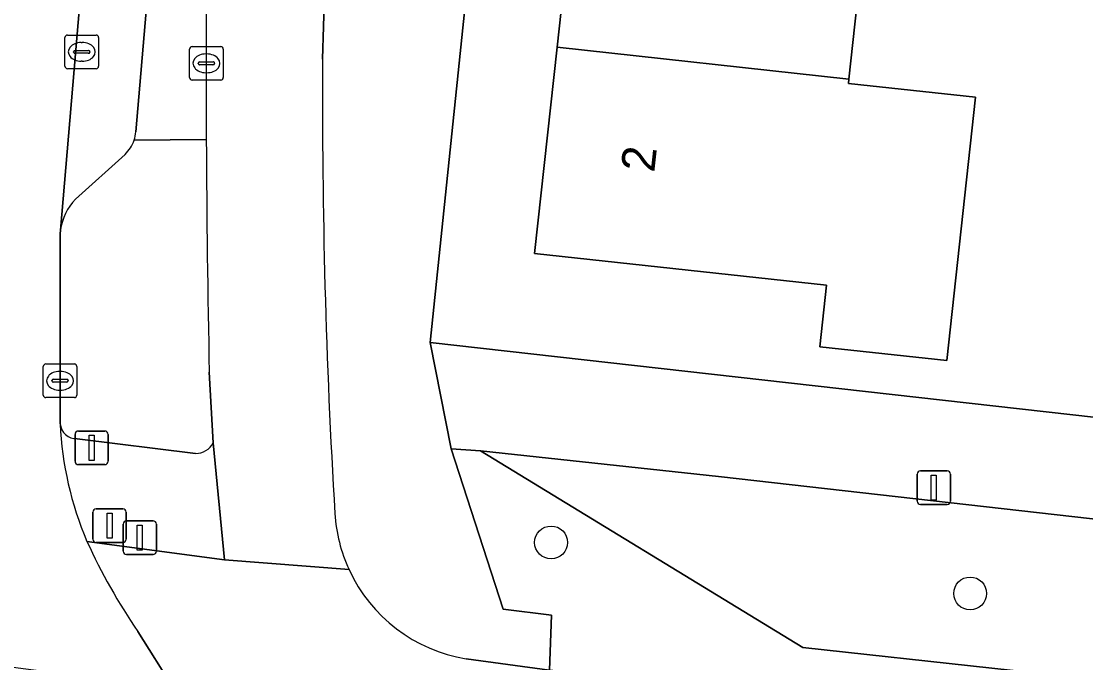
# Model space of a CAD drawing. Extents: x 161928 to 163071, y 386474 to 387428.
# Drawn here: x 162189.6 to 162221.3, y 386515.81 to 386534.9 of the extents above; entities that cross this region are included whole.
import ezdxf

# ---------------------------------------------------------------- set-up
doc = ezdxf.new("R2010")
doc.units = 0
for name, color, linetype in [('IMGEO_Boom', 7, 'Continuous'), ('IMGEO_Drukknoppaal', 7, 'Continuous'), ('IMGEO_Erf', 7, 'Continuous'), ('IMGEO_Fietspad_gesloten', 7, 'Continuous'), ('IMGEO_Gemengd_bos', 7, 'Continuous'), ('IMGEO_Groenvoorziening', 7, 'Continuous'), ('IMGEO_Kolk', 7, 'Continuous'), ('IMGEO_Lichtmast', 7, 'Continuous'), ('IMGEO_Muur', 7, 'Continuous'), ('IMGEO_Pand', 7, 'Continuous'), ('IMGEO_Pand_nummerreeks', 7, 'Continuous'), ('IMGEO_Parkeervlak_open', 7, 'Continuous'), ('IMGEO_Rijbaan_lokaal_gesloten', 7, 'Continuous'), ('IMGEO_Verkeerseiland_groen', 7, 'Continuous'), ('IMGEO_Verkeersregelinstallatiepaal', 7, 'Continuous'), ('IMGEO_Voetpad_open', 7, 'Continuous')]:
    doc.layers.add(name, color=color, linetype=linetype)

msp = doc.modelspace()

# ---------------------------------------------------------------- linework, layer by layer
at = {"layer": 'IMGEO_Boom'}
for centre in [(162205.374, 386519.388), (162217.854, 386517.87)]:
    msp.add_circle(centre, 0.489, dxfattribs=at)
at = {"layer": 'IMGEO_Drukknoppaal'}
for p, q in [((162192.629, 386519.13), (162192.629, 386519.93)), ((162192.629, 386519.93), (162192.629, 386519.13)), ((162192.729, 386520.03), (162193.519, 386520.03)), ((162193.519, 386520.03), (162192.729, 386520.03)), ((162193.619, 386519.93), (162193.619, 386519.13)), ((162193.619, 386519.13), (162193.619, 386519.93)), ((162193.519, 386519.03), (162192.729, 386519.03)), ((162192.729, 386519.03), (162193.519, 386519.03))]:
    msp.add_line(p, q, dxfattribs=at)
msp.add_lwpolyline([(162193.049, 386519.905), (162193.199, 386519.905), (162193.199, 386519.155), (162193.049, 386519.155), (162193.049, 386519.905)], dxfattribs=at)
for centre, start, end in [((162192.729, 386519.93), 90, 180), ((162192.729, 386519.93), 90, 180), ((162193.519, 386519.93), 0, 90), ((162193.519, 386519.93), 360, 90), ((162192.729, 386519.13), 180, 270), ((162192.729, 386519.13), 180, 270), ((162193.519, 386519.13), 270, 0), ((162193.519, 386519.13), 270, 0)]:
    msp.add_arc(centre, 0.1, start, end, dxfattribs=at)
at = {"layer": 'IMGEO_Erf'}
for points in [[(162225.896, 386540.19), (162223.328, 386540.475), (162223.755, 386544.322), (162224.185, 386548.197), (162226.753, 386547.912), (162227.231, 386552.252), (162224.663, 386552.537), (162225.087, 386556.355), (162225.516, 386560.226), (162227.822, 386559.97), (162228.384, 386565.127), (162215.553, 386566.525), (162206.218, 386567.564), (162205.437, 386560.624), (162201.776, 386525.342), (162223.909, 386522.85), (162224.507, 386528.163), (162221.939, 386528.448), (162222.366, 386532.295), (162222.796, 386536.17), (162225.364, 386535.885)], [(162214.898, 386539.2), (162214.243, 386533.186), (162214.229, 386533.056), (162218.017, 386532.643), (162217.163, 386524.802), (162213.375, 386525.215), (162213.574, 386527.044), (162204.885, 386527.99), (162205.554, 386534.133), (162206.209, 386540.147), (162206.864, 386546.162), (162207.519, 386552.176), (162208.174, 386558.19), (162208.843, 386564.333), (162217.515, 386563.389), (162216.846, 386557.247), (162220.094, 386556.893), (162219.441, 386550.903), (162216.208, 386551.229), (162215.553, 386545.215)]]:
    msp.add_lwpolyline(points, close=True, dxfattribs=at)
at = {"layer": 'IMGEO_Fietspad_gesloten'}
for points in [[(162198.57, 386533.782), (162198.628, 386535.734), (162198.696, 386542.751), (162199.142, 386551.545), (162199.698, 386559.354)], [(162195.195, 386524.457), (162195.312, 386522.354), (162195.653, 386518.869), (162199.358, 386518.579)], [(162199.358, 386518.579), (162195.653, 386518.869), (162191.551, 386519.42)], [(162193.066, 386516.739), (162194.132, 386515.055)], [(162249.57, 386510.502), (162212.718, 386514.865), (162205.323, 386515.589), (162202.846, 386515.924)]]:
    msp.add_lwpolyline(points, dxfattribs=at)
for centre, radius, start, end in [((162647.939, 386533.912), 452.84, 178.75419, 180.31954), ((162402.165, 386532.502), 203.599, 179.63972, 183.4502), ((162639.892, 386533.634), 444.792, 180.28941, 181.18218), ((162203.615, 386520.546), 4.689, 183.6288, 204.7987), ((162208.114, 386527.011), 18.219, 204.6223, 214.3182), ((162203.61, 386520.546), 4.685, 204.8292, 260.6154)]:
    msp.add_arc(centre, radius, start, end, dxfattribs=at)
at = {"layer": 'IMGEO_Gemengd_bos'}
msp.add_lwpolyline([(162244.314, 386517.547), (162224.653, 386519.735), (162210.364, 386521.35), (162203.272, 386522.117), (162212.87, 386516.261), (162224.131, 386515.029), (162243.789, 386512.877)], close=True, dxfattribs=at)
at = {"layer": 'IMGEO_Groenvoorziening'}
msp.add_lwpolyline([(162380.871, 386491.346), (162381.458, 386496.265), (162381.983, 386500), (162382.205, 386501.975), (162371.516, 386503.188), (162370.953, 386498.22), (162297.494, 386506.509), (162297.39, 386505.635), (162272.624, 386508.235), (162272.737, 386509.296), (162259.637, 386510.771), (162256.748, 386511.459), (162243.789, 386512.877), (162224.131, 386515.029), (162212.87, 386516.261), (162203.272, 386522.117), (162202.401, 386522.176), (162203.943, 386517.405), (162205.389, 386517.222), (162205.323, 386515.589), (162212.718, 386514.865), (162249.57, 386510.502)], dxfattribs=at)
at = {"layer": 'IMGEO_Kolk'}
for p, q in [((162190.896, 386533.568), (162190.896, 386534.42)), ((162190.971, 386534.494), (162191.823, 386534.494)), ((162191.897, 386534.42), (162191.897, 386533.568)), ((162191.384, 386534.274), (162191.409, 386534.274)), ((162194.684, 386534.153), (162195.536, 386534.153)), ((162191.155, 386533.988), (162191.155, 386534)), ((162191.593, 386533.951), (162191.195, 386533.951)), ((162191.198, 386534.037), (162191.596, 386534.037)), ((162191.639, 386534), (162191.639, 386533.988)), ((162194.609, 386533.227), (162194.609, 386534.079)), ((162195.097, 386533.933), (162195.122, 386533.933)), ((162195.61, 386534.079), (162195.61, 386533.227)), ((162191.823, 386533.494), (162190.971, 386533.494)), ((162191.407, 386533.714), (162191.382, 386533.714)), ((162194.868, 386533.647), (162194.868, 386533.659)), ((162195.306, 386533.61), (162194.908, 386533.61)), ((162194.911, 386533.696), (162195.309, 386533.696)), ((162195.352, 386533.659), (162195.352, 386533.647)), ((162195.536, 386533.153), (162194.684, 386533.153)), ((162195.12, 386533.373), (162195.095, 386533.373)), ((162190.25, 386523.776), (162190.25, 386524.628)), ((162190.325, 386524.702), (162191.177, 386524.702)), ((162191.251, 386524.628), (162191.251, 386523.776)), ((162190.738, 386524.482), (162190.763, 386524.482)), ((162190.509, 386524.196), (162190.509, 386524.208)), ((162190.947, 386524.159), (162190.549, 386524.159)), ((162190.552, 386524.245), (162190.95, 386524.245)), ((162190.993, 386524.208), (162190.993, 386524.196)), ((162191.177, 386523.702), (162190.325, 386523.702)), ((162190.761, 386523.922), (162190.736, 386523.922))]:
    msp.add_line(p, q, dxfattribs=at)
for points in [[(162190.896, 386533.568), (162190.896, 386534.42)], [(162190.971, 386534.494), (162191.823, 386534.494)], [(162191.897, 386534.42), (162191.897, 386533.568)], [(162194.684, 386534.153), (162195.536, 386534.153)], [(162194.609, 386533.227), (162194.609, 386534.079)], [(162195.61, 386534.079), (162195.61, 386533.227)], [(162191.823, 386533.494), (162190.971, 386533.494)], [(162195.536, 386533.153), (162194.684, 386533.153)], [(162190.25, 386523.776), (162190.25, 386524.628)], [(162190.325, 386524.702), (162191.177, 386524.702)], [(162191.251, 386524.628), (162191.251, 386523.776)], [(162191.177, 386523.702), (162190.325, 386523.702)]]:
    msp.add_lwpolyline(points, dxfattribs=at)
for centre, radius, start, end in [((162190.973, 386534.418), 0.0765, 91.552, 178.448), ((162190.973, 386534.418), 0.0765, 91.552, 178.448), ((162191.821, 386534.418), 0.0765, 1.552, 88.448), ((162191.821, 386534.418), 0.0765, 1.552, 88.448), ((162194.686, 386534.077), 0.0765, 91.552, 178.448), ((162194.686, 386534.077), 0.0765, 91.552, 178.448), ((162195.534, 386534.077), 0.0765, 1.552, 88.448), ((162195.534, 386534.077), 0.0765, 1.552, 88.448), ((162191.195, 386533.997), 0.0403, 85.8775, 175.7526), ((162191.192, 386533.987), 0.0366, 178.938, 274.7102), ((162191.596, 386533.994), 0.043, 264.8664, 352.4533), ((162191.6, 386533.999), 0.0386, 1.7309, 96.639), ((162190.973, 386533.57), 0.0765, 181.552, 268.448), ((162190.973, 386533.57), 0.0765, 181.552, 268.448), ((162191.821, 386533.57), 0.0765, 271.552, 358.448), ((162191.821, 386533.57), 0.0765, 271.552, 358.448), ((162194.908, 386533.656), 0.0403, 85.8775, 175.7526), ((162194.905, 386533.646), 0.0366, 178.938, 274.7102), ((162195.309, 386533.653), 0.043, 264.8664, 352.4533), ((162195.313, 386533.658), 0.0386, 1.7309, 96.639), ((162194.686, 386533.229), 0.0765, 181.552, 268.448), ((162194.686, 386533.229), 0.0765, 181.552, 268.448), ((162195.534, 386533.229), 0.0765, 271.552, 358.448), ((162195.534, 386533.229), 0.0765, 271.552, 358.448), ((162190.327, 386524.626), 0.0765, 91.552, 178.448), ((162190.327, 386524.626), 0.0765, 91.552, 178.448), ((162191.175, 386524.626), 0.0765, 1.552, 88.448), ((162191.175, 386524.626), 0.0765, 1.552, 88.448), ((162190.549, 386524.205), 0.0403, 85.8775, 175.7526), ((162190.546, 386524.195), 0.0366, 178.938, 274.7102), ((162190.95, 386524.202), 0.043, 264.8664, 352.4533), ((162190.954, 386524.207), 0.0386, 1.7309, 96.639), ((162190.327, 386523.778), 0.0765, 181.552, 268.448), ((162190.327, 386523.778), 0.0765, 181.552, 268.448), ((162191.175, 386523.778), 0.0765, 271.552, 358.448), ((162191.175, 386523.778), 0.0765, 271.552, 358.448)]:
    msp.add_arc(centre, radius, start, end, dxfattribs=at)
for centre, major_axis, ratio, start_param, end_param in [((162191.383, 386533.994), (-0.387, 0.002), 0.722429, 4.712389, 7.853982), ((162191.408, 386533.994), (-0.39, 0.002), 0.717154, 1.570796, 4.712389), ((162195.096, 386533.653), (-0.387, 0.002), 0.722429, 4.712389, 7.853982), ((162195.121, 386533.653), (-0.39, 0.002), 0.717154, 1.570796, 4.712389), ((162190.737, 386524.202), (-0.387, 0.002), 0.722429, 4.712389, 7.853982), ((162190.762, 386524.202), (-0.39, 0.002), 0.717154, 1.570796, 4.712389)]:
    msp.add_ellipse(centre, major_axis=major_axis, ratio=ratio, start_param=start_param, end_param=end_param, dxfattribs=at)
at = {"layer": 'IMGEO_Lichtmast'}
for p, q in [((162216.377, 386521.521), (162217.167, 386521.521)), ((162217.167, 386521.521), (162216.377, 386521.521)), ((162216.277, 386520.621), (162216.277, 386521.421)), ((162216.277, 386521.421), (162216.277, 386520.621)), ((162217.267, 386521.421), (162217.267, 386520.621)), ((162217.267, 386520.621), (162217.267, 386521.421)), ((162217.167, 386520.521), (162216.377, 386520.521)), ((162216.377, 386520.521), (162217.167, 386520.521))]:
    msp.add_line(p, q, dxfattribs=at)
msp.add_lwpolyline([(162216.697, 386521.396), (162216.847, 386521.396), (162216.847, 386520.646), (162216.697, 386520.646), (162216.697, 386521.396)], dxfattribs=at)
for centre, start, end in [((162216.377, 386521.421), 90, 180), ((162216.377, 386521.421), 90, 180), ((162217.167, 386521.421), 0, 90), ((162217.167, 386521.421), 360, 90), ((162216.377, 386520.621), 180, 270), ((162216.377, 386520.621), 180, 270), ((162217.167, 386520.621), 270, 0), ((162217.167, 386520.621), 270, 0)]:
    msp.add_arc(centre, 0.1, start, end, dxfattribs=at)
at = {"layer": 'IMGEO_Muur'}
msp.add_lwpolyline([(162224.131, 386515.029), (162212.87, 386516.261), (162203.272, 386522.117)], dxfattribs=at)
at = {"layer": 'IMGEO_Pand'}
for points in [[(162214.243, 386533.186), (162214.898, 386539.2), (162206.209, 386540.147), (162205.554, 386534.133)], [(162218.017, 386532.643), (162214.229, 386533.056), (162214.243, 386533.186), (162205.554, 386534.133), (162204.885, 386527.99), (162213.574, 386527.044), (162213.375, 386525.215), (162217.163, 386524.802)]]:
    msp.add_lwpolyline(points, close=True, dxfattribs=at)
at = {"layer": 'IMGEO_Parkeervlak_open'}
for points in [[(162194.054, 386567.097), (162194.059, 386567.197), (162194.032, 386566.972), (162191.971, 386542.925), (162190.764, 386528.691)], [(162193.009, 386531.614), (162195.93, 386565.697)], [(162191.207, 386529.605), (162192.688, 386530.94)]]:
    msp.add_lwpolyline(points, dxfattribs=at)
for centre, radius, start, end in [((162191.905, 386531.716), 1.109, 341.5973, 354.7185), ((162191.944, 386531.708), 1.069, 314.1001, 341.3587), ((162192.405, 386528.46), 1.658, 136.2996, 171.9831)]:
    msp.add_arc(centre, radius, start, end, dxfattribs=at)
at = {"layer": 'IMGEO_Rijbaan_lokaal_gesloten'}
for points in [[(162187.844, 386542.738), (162186.725, 386532.259), (162186.765, 386531.963), (162185.853, 386523.553), (162185.469, 386520.1), (162185.253, 386518.103), (162184.943, 386516.254), (162194.132, 386515.055), (162193.066, 386516.739)], [(162190.752, 386522.922), (162190.754, 386528.578), (162190.764, 386528.691), (162191.971, 386542.925)]]:
    msp.add_lwpolyline(points, dxfattribs=at)
for centre, radius, start, end in [((162200.865, 386523.387), 10.123, 182.6334, 203.0712), ((162208.114, 386527.011), 18.219, 204.6223, 214.3182)]:
    msp.add_arc(centre, radius, start, end, dxfattribs=at)
at = {"layer": 'IMGEO_Verkeerseiland_groen'}
for points in [[(162195.106, 386531.387), (162192.957, 386531.366)], [(162192.688, 386530.94), (162191.207, 386529.605)], [(162190.764, 386528.691), (162190.754, 386528.578), (162190.752, 386522.922)], [(162195.312, 386522.354), (162195.195, 386524.457)], [(162191.258, 386522.478), (162194.789, 386522.034)]]:
    msp.add_lwpolyline(points, dxfattribs=at)
for centre, radius, start, end in [((162191.944, 386531.708), 1.069, 314.1001, 341.3587), ((162639.892, 386533.634), 444.792, 180.28941, 181.18218), ((162192.405, 386528.46), 1.658, 136.2996, 171.9831), ((162191.235, 386522.962), 0.484, 184.723, 272.7451), ((162194.772, 386522.649), 0.615, 271.5487, 331.3725)]:
    msp.add_arc(centre, radius, start, end, dxfattribs=at)
at = {"layer": 'IMGEO_Verkeersregelinstallatiepaal'}
for p, q in [((162191.296, 386522.706), (162192.086, 386522.706)), ((162192.086, 386522.706), (162191.296, 386522.706)), ((162191.196, 386521.806), (162191.196, 386522.606)), ((162191.196, 386522.606), (162191.196, 386521.806)), ((162192.186, 386522.606), (162192.186, 386521.806)), ((162192.186, 386521.806), (162192.186, 386522.606)), ((162192.086, 386521.706), (162191.296, 386521.706)), ((162191.296, 386521.706), (162192.086, 386521.706)), ((162191.729, 386519.488), (162191.729, 386520.288)), ((162191.729, 386520.288), (162191.729, 386519.488)), ((162191.829, 386520.388), (162192.619, 386520.388)), ((162192.619, 386520.388), (162191.829, 386520.388)), ((162192.719, 386520.288), (162192.719, 386519.488)), ((162192.719, 386519.488), (162192.719, 386520.288)), ((162192.619, 386519.388), (162191.829, 386519.388)), ((162191.829, 386519.388), (162192.619, 386519.388))]:
    msp.add_line(p, q, dxfattribs=at)
for points in [[(162191.616, 386522.581), (162191.766, 386522.581), (162191.766, 386521.831), (162191.616, 386521.831), (162191.616, 386522.581)], [(162192.149, 386520.263), (162192.299, 386520.263), (162192.299, 386519.513), (162192.149, 386519.513), (162192.149, 386520.263)]]:
    msp.add_lwpolyline(points, dxfattribs=at)
for centre, start, end in [((162191.296, 386522.606), 90, 180), ((162191.296, 386522.606), 90, 180), ((162192.086, 386522.606), 0, 90), ((162192.086, 386522.606), 360, 90), ((162191.296, 386521.806), 180, 270), ((162191.296, 386521.806), 180, 270), ((162192.086, 386521.806), 270, 0), ((162192.086, 386521.806), 270, 0), ((162191.829, 386520.288), 90, 180), ((162191.829, 386520.288), 90, 180), ((162192.619, 386520.288), 0, 90), ((162192.619, 386520.288), 360, 90), ((162191.829, 386519.488), 180, 270), ((162191.829, 386519.488), 180, 270), ((162192.619, 386519.488), 270, 0), ((162192.619, 386519.488), 270, 0)]:
    msp.add_arc(centre, 0.1, start, end, dxfattribs=at)
at = {"layer": 'IMGEO_Voetpad_open'}
for points in [[(162202.846, 386515.924), (162205.323, 386515.589), (162205.389, 386517.222), (162203.943, 386517.405), (162202.401, 386522.176), (162201.776, 386525.342), (162205.437, 386560.624), (162206.218, 386567.564), (162206.668, 386570.539), (162205.635, 386570.627), (162206.334, 386577.664)], [(162195.93, 386565.697), (162193.009, 386531.614)], [(162198.628, 386535.734), (162198.57, 386533.782)], [(162192.957, 386531.366), (162195.106, 386531.387)], [(162245.671, 386520.399), (162225.221, 386522.702), (162223.909, 386522.85), (162201.776, 386525.342), (162202.401, 386522.176), (162203.272, 386522.117), (162210.364, 386521.35), (162224.653, 386519.735), (162244.314, 386517.547), (162273.275, 386514.324), (162298.087, 386511.519), (162347.162, 386505.951), (162371.516, 386503.188), (162382.205, 386501.975), (162382.604, 386505.469), (162378.144, 386505.94), (162375.565, 386506.213), (162368.502, 386506.62), (162368.281, 386506.633), (162347.875, 386508.944), (162346.386, 386509.112), (162326.011, 386511.421)], [(162194.789, 386522.034), (162191.258, 386522.478)], [(162191.551, 386519.42), (162195.653, 386518.869), (162195.312, 386522.354)]]:
    msp.add_lwpolyline(points, dxfattribs=at)
for centre, radius, start, end in [((162647.939, 386533.912), 452.84, 178.75419, 180.31954), ((162402.165, 386532.502), 203.599, 179.63972, 183.4502), ((162191.905, 386531.716), 1.109, 341.5973, 354.7185), ((162191.235, 386522.962), 0.484, 184.723, 272.7451), ((162200.865, 386523.387), 10.123, 182.6334, 203.0712), ((162194.772, 386522.649), 0.615, 271.5487, 331.3725), ((162203.615, 386520.546), 4.689, 183.6288, 204.7987), ((162203.61, 386520.546), 4.685, 204.8292, 260.6154)]:
    msp.add_arc(centre, radius, start, end, dxfattribs=at)

# ---------------------------------------------------------------- texts
at = {"layer": 'IMGEO_Pand_nummerreeks'}
msp.add_text('2', height=1, rotation=83.7836, dxfattribs=at).set_placement((162208.446, 386530.388))

doc.saveas('drawing.dxf')
